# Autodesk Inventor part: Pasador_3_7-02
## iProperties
Created: 2008-01
Part Number: Pasador_3_7-02
Material: ABS Plastic
Document SubType Name: Modeling
Designer: eruiz-tagle
Mass: 0.469838 g
Surface Area: 7.17072 cm^2
Volume: 0.443244 cm^3
Density: 1.06 g/cm^3
Company: COMGRAP
Title: CURSO INVENTOR
Author: Esteban
Comments: Esta pieza fue creada en el curso de inventor
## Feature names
1. Derived Body1 [Tagging]
